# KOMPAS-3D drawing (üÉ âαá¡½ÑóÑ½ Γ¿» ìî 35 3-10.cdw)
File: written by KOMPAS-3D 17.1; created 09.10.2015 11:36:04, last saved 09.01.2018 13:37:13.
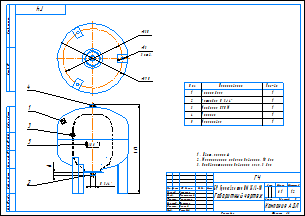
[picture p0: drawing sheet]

Sheet 1: A3, landscape

Title block, sheet 1: name: БР Гранлевел тип НМ 35/3-10 / Габаритный чертеж; mass: 6.1; scale: 1:2; sheets: 1; organisation: Компания АДЛ; cell 10: Нач.отд.; sheet format: A3; stored path: \\Fsk1.adlc.lan\files\АП\20_PKO\02_Насосное направление\АУПД\Чертежи на баки\Чертеж.cdw; drawn by: Лощинин; checked by: Хантимеров; technical control: Курлыкина; cell 113: Щетинин; standards control: Долгов; approved by: Рашидов

Views: Вид 3, Спереди, Проекционный вид 4
Referenced files in \\Fsk1\FILES\АП\20_PKO\02_Насосное направление\Разработка\04_Проекты разные\Баки\КД действующая\flexcon r_dwg\Компас\: 35 литров.a3d, 8 литров.a3d
Referenced files in \\Fsk1\files\АП\20_PKO\02_Насосное направление\Разработка\04_Проекты разные\Баки\КД действующая\Баки Flexcon R\Компас\: 35 литров.a3d
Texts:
  ADL
  romans
  romand
  romant
  АДЛ
  БР Гранлевел тип НМ 35/1,5-6
  TRAZO_Y_PUNTOX2_RGB_0_255_0_SC_2_THICK_0.05
  TRAZO_Y_PUNTOX2_RGB_0_255_0_SC_1_THICK_0.05
  TRAZO_Y_PUNTOX2_RGB_0_255_0_SC_0.3_THICK_0.05
  POLYLINE_STYLE_0.30_RGB_0_0_0
  ACAD_ISO03W100_RGB_223_127_255_SC_0.5_THICK_0.05
  ACAD_ISO03W100_RGB_223_127_255_SC_1_THICK_0.05
  TRAZO_Y_PUNTOX2_RGB_0_255_0_SC_0.25_THICK_0.05
  СONTINUOUS_RGB_223_127_255_THICK_0.05
  ACAD_ISO03W100_RGB_223_127_255_SC_0.25_THICK_0.05
  TRAZO_Y_PUNTOX2_RGB_0_255_0_SC_3_THICK_0.05
  POLYLINE_STYLE_0.35_RGB_0_0_0
  TRAZO_Y_PUNTOX2_RGB_0_255_0_SC_0.5_THICK_0.05
  TRAZO_Y_PUNTOX2_RGB_0_255_0_SC_0.4_THICK_0.05
  ACAD_ISO03W100_RGB_223_127_255_SC_0.046_THICK_0.05
  ACAD_ISO03W100_RGB_223_127_255_SC_0.24_THICK_0.05
  ACAD_ISO03W100_RGB_223_127_255_SC_0.15_THICK_0.05
  ACAD_ISO03W100_RGB_223_127_255_SC_0.0081_THICK_0.05
  ACAD_ISO03W100_RGB_223_127_255_SC_0.0092_THICK_0.05
  ACAD_ISO03W100_RGB_223_127_255_SC_0.14_THICK_0.05
  ACAD_ISO03W100_RGB_223_127_255_SC_0.16_THICK_0.05
  ACAD_ISO03W100_RGB_223_127_255_SC_0.31_THICK_0.05
  ACAD_ISO03W100_RGB_223_127_255_SC_0.47_THICK_0.05
  ACAD_ISO03W100_RGB_223_127_255_SC_0.26_THICK_0.05
  ACAD_ISO03W100_RGB_223_127_255_SC_0.36_THICK_0.05
  CONTINUOUS_RGB_0_0_0_THICK_0.3
  ACAD_ISO03W100_RGB_223_127_255_SC_0.027_THICK_0.05
  ACAD_ISO03W100_RGB_223_127_255_SC_0.18_THICK_0.05
  ACAD_ISO03W100_RGB_223_127_255_SC_0.4_THICK_0.05
  ACAD_ISO03W100_RGB_223_127_255_SC_0.016_THICK_0.05
  ACAD_ISO03W100_RGB_223_127_255_SC_0.057_THICK_0.05
  ACAD_ISO03W100_RGB_223_127_255_SC_0.23_THICK_0.05
  ACAD_ISO03W100_RGB_223_127_255_SC_0.011_THICK_0.05
  ACAD_ISO03W100_RGB_223_127_255_SC_0.42_THICK_0.05
  ACAD_ISO03W100_RGB_223_127_255_SC_0.29_THICK_0.05
  ACAD_ISO03W100_RGB_223_127_255_SC_0.061_THICK_0.05
  ACAD_ISO03W100_RGB_223_127_255_SC_0.32_THICK_0.05
  ACAD_ISO03W100_RGB_223_127_255_SC_0.002_THICK_0.05
  ACAD_ISO03W100_RGB_223_127_255_SC_0.065_THICK_0.05
  ACAD_ISO03W100_RGB_223_127_255_SC_0.28_THICK_0.05
  ACAD_ISO03W100_RGB_223_127_255_SC_0.058_THICK_0.05
  ACAD_ISO03W100_RGB_223_127_255_SC_0.022_THICK_0.05
  ACAD_ISO03W100_RGB_223_127_255_SC_0.0055_THICK_0.05
  ACAD_ISO03W100_RGB_223_127_255_SC_0.19_THICK_0.05
  ACAD_ISO03W100_RGB_223_127_255_SC_0.22_THICK_0.05
  ACAD_ISO03W100_RGB_223_127_255_SC_0.12_THICK_0.05
  ACAD_ISO03W100_RGB_223_127_255_SC_0.21_THICK_0.05
  ACAD_ISO03W100_RGB_223_127_255_SC_0.1_THICK_0.05
  CONTINUOUS_RGB_255_223_127_THICK_0.15
  ACAD_ISO03W100_RGB_223_127_255_SC_0.085_THICK_0.05
  ACAD_ISO03W100_RGB_223_127_255_SC_0.026_THICK_0.05
  ACAD_ISO03W100_RGB_223_127_255_SC_0.05_THICK_0.05
  ACAD_ISO03W100_RGB_223_127_255_SC_0.3_THICK_0.05
  ACAD_ISO03W100_RGB_223_127_255_SC_0.33_THICK_0.05
  ACAD_ISO03W100_RGB_223_127_255_SC_0.49_THICK_0.05
  ACAD_ISO03W100_RGB_223_127_255_SC_0.37_THICK_0.05
  ACAD_ISO03W100_RGB_223_127_255_SC_0.035_THICK_0.05
  ACAD_ISO03W100_RGB_223_127_255_SC_0.018_THICK_0.05
  ACAD_ISO03W100_RGB_223_127_255_SC_0.45_THICK_0.05
  ACAD_ISO03W100_RGB_223_127_255_SC_0.051_THICK_0.05
  CONTINUOUS_RGB_255_0_0_THICK_0.05
  CONTINUOUS_RGB_255_191_0_THICK_0.05
  TRAZO_Y_PUNTOX2_RGB_0_255_0_SC_0.13_THICK_0.05
  CONTINUOUS_RGB_191_255_127_THICK_0.05
  ACAD_ISO03W100_RGB_223_127_255_SC_0.042_THICK_0.05
  ACAD_ISO03W100_RGB_223_127_255_SC_0.27_THICK_0.05
  ACAD_ISO03W100_RGB_223_127_255_SC_0.0016_THICK_0.05
  ACAD_ISO03W100_RGB_223_127_255_SC_0.099_THICK_0.05
  ACAD_ISO03W100_RGB_223_127_255_SC_0.0058_THICK_0.05
  ACAD_ISO03W100_RGB_223_127_255_SC_0.0074_THICK_0.05
  ACAD_ISO03W100_RGB_223_127_255_SC_0.088_THICK_0.05
  ACAD_ISO03W100_RGB_223_127_255_SC_0.0023_THICK_0.05
  ACAD_ISO03W100_RGB_223_127_255_SC_0.38_THICK_0.05
  ACAD_ISO03W100_RGB_223_127_255_SC_0.093_THICK_0.05
  ACAD_ISO03W100_RGB_223_127_255_SC_0.34_THICK_0.05
  ACAD_ISO03W100_RGB_223_127_255_SC_0.087_THICK_0.05
  ACAD_ISO03W100_RGB_223_127_255_SC_0.015_THICK_0.05
  ACAD_ISO03W100_RGB_223_127_255_SC_0.2_THICK_0.05
  ACAD_ISO03W100_RGB_223_127_255_SC_0.41_THICK_0.05
  ACAD_ISO03W100_RGB_223_127_255_SC_0.35_THICK_0.05
  ACAD_ISO03W100_RGB_223_127_255_SC_0.0006_THICK_0.05
  ACAD_ISO03W100_RGB_223_127_255_SC_0.012_THICK_0.05
  CONTINUOUS_RGB_255_223_127_THICK_0.05
  TRAZO_Y_PUNTOX2_RGB_0_255_0_SC_0.35_THICK_0.05
  TRAZO_Y_PUNTOX2_RGB_0_255_0_SC_0.2_THICK_0.05
  TRAZO_Y_PUNTOX2_RGB_0_255_0_SC_0.08_THICK_0.05
  ACAD_ISO03W100_RGB_223_127_255_SC_0.8_THICK_0.05
  TRAZO_Y_PUNTOX2_RGB_0_255_0_SC_0.75_THICK_0.05
  ACAD_ISO03W100_RGB_223_127_255_SC_0.13_THICK_0.05
  ACAD_ISO03W100_RGB_223_127_255_SC_0.063_THICK_0.05
  TRAZO_Y_PUNTOX2_RGB_0_255_0_SC_0.11_THICK_0.05
  HOUND_ISO 0
  HOUND_ISO 1
  ANGLE_ISO 0
  ANGLE_ISO 1
  AR-CONC_ISO
  AR-CONC_ISO 0
  AR-CONC_ISO 1
  AR-CONC_ISO 2
  AR-CONC_ISO 3
  AR-CONC_ISO 4
  AR-CONC_ISO 5
  AR-CONC_ISO 6
  AR-CONC_ISO 7
  AR-CONC_ISO 8
  AR-CONC_ISO 9
  AR-CONC_ISO 10
  AR-CONC_ISO 11
  AR-CONC_ISO 12
  ANSI38_ISO 1
Dimensions and other numbers on the sheet: 496; 16; 330; 390; 13; 3 отв.; 1:2; 1; 6.1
